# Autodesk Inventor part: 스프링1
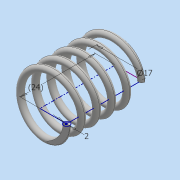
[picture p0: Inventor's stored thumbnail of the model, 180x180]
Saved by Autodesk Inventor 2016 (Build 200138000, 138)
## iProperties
Created: 2019-11
Part Number: 스프링1
Material: 일반
Document SubType Name: Modeling
Designer: user
Density: 1 g/cm^3
Appearance: 기본값
Mass: 0.821961 g
Surface Area: 16.7192 cm^2
Volume: 0.821961 cm^3
Author: user
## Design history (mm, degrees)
sketch "스케치1"
  geometry: L1 (0, 0)-(8.5, 0); L2 (8.5, 0)-(8.5, 20.5); L3 (8.5, 20.5)-(0, 20.5); L4 (0, 20.5)-(0, 0); C1 r 1 at (8.5, 0)
  constraints: 8 end point, 2 parallel, 1 centre point, 1 coincident, 1 horizontal, 1 perpendicular
  dimensions: "d0" = 17 diameter of L2 L4; "d1" = 20.5 distance between parallel lines of L1 L3 (derived); "d2" = 2 diameter of C1
feature "코일1" sketch "스케치1" pitch "d3" = 10; turns "d5" = 5; dims "d4" = 20.5 (= d1), "d6" = 0, angle "d7" = 90 deg, angle "d8" = 90 deg, "d9" = 0, "d10" = 0
sketch "스케치2"
  geometry: L1 (-11.228, 0)-(11.228, 0); L2 (11.228, 0)-(11.228, 20.5); L3 (11.228, 20.5)-(-11.228, 20.5); L4 (-11.228, 20.5)-(-11.228, 0); 2 further points
  constraints: 8 end point, 2 parallel, 1 coincident, 1 horizontal, 1 midpoint, 1 perpendicular
  dimensions: "d11" = 20.5 distance between parallel lines of L1 L3 (= d1); "d12" = 22.45649 distance between parallel lines of L2 L4
extrude "돌출1" sketch "스케치2" stored distance "d13" = 42.25; taper "d14" = 0 deg
node "솔리드1"
